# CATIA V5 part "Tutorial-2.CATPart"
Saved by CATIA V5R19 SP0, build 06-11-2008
Part number: c02tut2
Bounding box of the stored display mesh (mm): x 0 to 0, y -39.994 to 149.998, z -39.999 to 39.984
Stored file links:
  D:\Shriniwas\v5_r19\Part files\c03\c03tut2.CATPart
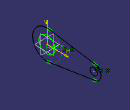
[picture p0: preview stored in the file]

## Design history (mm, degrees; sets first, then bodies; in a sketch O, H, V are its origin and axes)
Body1 (main body)
  Sketch1 on yz-plane, origin (0, 0, 0), H (0, 1, 0), V (0, 0, 1)
    arc A1 centre (0, 0) radius 40 from (6.1538, 39.5238) to (6.1538, -39.5238) ccw
    point P1 (40, 0)
    arc A2 centre (130, 0) radius 20 from (133.0769, -19.7619) to (133.0769, 19.7619) ccw
    point P2 (130, 0)
    line L1 (133.0769, 19.7619) -> (6.1538, 39.5238)
    line L2 (6.1538, -39.5238) -> (133.0769, -19.7619)
    circle A3 centre (0, 0) radius 22.5
    circle A4 centre (130, 0) radius 10
    point P7 (140, 0)
    radius A3 = 22.5
    coincidence: A1 P1, P1 H, P2 H, A4 P7, P7 H
    tangency: L1 A2, L1 A1, L2 A1, L2 A2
